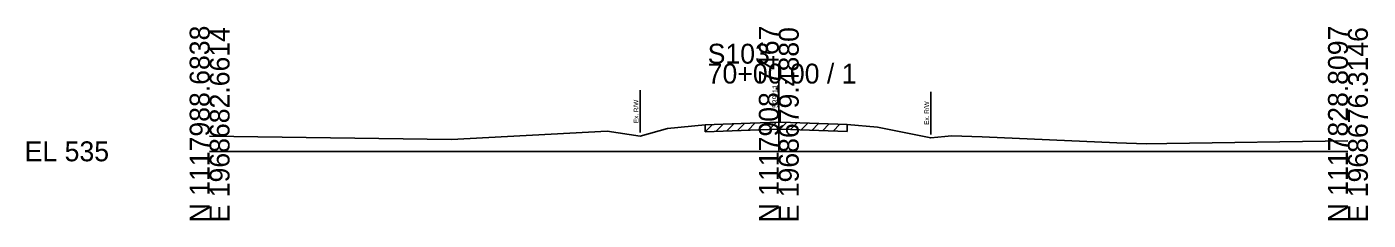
# Model space of a CAD drawing. Extents: x -26 to 163, y -10 to 24018.
# Drawn here: x -25.7 to 162.8, y 17990.3 to 18017.5 of the extents above; entities that cross this region are included whole.
import ezdxf

# ---------------------------------------------------------------- set-up
doc = ezdxf.new("R2010")
doc.units = 0
for name, color, linetype in [('RD_GPK_XS_Cell', 7, 'Continuous'), ('RD_XS_ExGround', 7, 'Continuous'), ('RD_XS_ExPaveRet', 7, 'Continuous'), ('RD_XS_ExRW', 7, 'Continuous'), ('RD_XS_TX_Elev_EX', 7, 'Continuous')]:
    doc.layers.add(name, color=color, linetype=linetype)

msp = doc.modelspace()

# ---------------------------------------------------------------- linework, layer by layer
at = {"layer": 'RD_GPK_XS_Cell'}
for p, q in [((80, 18000), (80, 18012.34)), ((0, 18000), (80, 18000)), ((80, 18000), (160, 18000))]:
    msp.add_line(p, q, dxfattribs=at)
at = {"layer": 'RD_XS_ExGround'}
msp.add_lwpolyline([(0, 18002.15), (33.98, 18001.68), (55.86, 18002.84), (60.51, 18002.13), (64.34, 18003.21), (69.63, 18003.74), (75.97, 18003.96), (80.14, 18004.11), (81.66, 18004.06), (89.61, 18003.77), (93.87, 18003.39), (101.36, 18001.89), (103.33, 18002.1), (104.26, 18002.2), (108.59, 18002.02), (127.49, 18001.22), (131.62, 18001.04), (134.56, 18001.08), (160, 18001.47)], dxfattribs=at)
at = {"layer": 'RD_XS_ExPaveRet'}
for p, q in [((69.63, 18002.74), (70.67, 18003.78)), ((69.63, 18002.74), (69.63, 18003.74)), ((71.13, 18002.79), (72.17, 18003.83)), ((72.63, 18002.85), (73.67, 18003.88)), ((74.13, 18002.9), (75.17, 18003.94)), ((75.63, 18002.95), (76.67, 18003.99)), ((75.97, 18002.96), (80.14, 18003.11)), ((77.13, 18003.01), (78.17, 18004.04)), ((78.63, 18003.06), (79.67, 18004.1)), ((80.13, 18003.11), (81.1, 18004.08)), ((80.14, 18003.11), (81.66, 18003.06)), ((81.63, 18003.06), (82.6, 18004.03)), ((81.66, 18003.06), (89.61, 18002.77)), ((83.13, 18003.01), (84.1, 18003.97)), ((84.63, 18002.95), (85.6, 18003.92)), ((86.13, 18002.9), (87.1, 18003.86)), ((87.63, 18002.84), (88.6, 18003.81)), ((89.61, 18003.77), (89.61, 18002.77)), ((69.63, 18002.74), (75.97, 18002.96))]:
    msp.add_line(p, q, dxfattribs=at)
at = {"layer": 'RD_XS_ExRW'}
for p, q in [((60.51, 18008.63), (60.51, 18002.63)), ((101.36, 18008.39), (101.36, 18002.39))]:
    msp.add_line(p, q, dxfattribs=at)

# ---------------------------------------------------------------- texts
at = {"layer": 'RD_GPK_XS_Cell'}
for s, p in [('N 1117988.6838', (0, 17990)), ('E 1968682.6614', (2.8, 17990)), ('N 1117908.7467', (80, 17990)), ('E 1968679.4880', (82.8, 17990)), ('N 1117828.8097', (160, 17990)), ('E 1968676.3146', (162.8, 17990))]:
    msp.add_text(s, height=2.8, rotation=90, dxfattribs=at).set_placement(p)
for s, p in [('S103', (70, 18012.34)), ('70+00.00 / 1', (70, 18009.54)), ('EL 535', (-26, 17998.6))]:
    msp.add_text(s, height=2.8, dxfattribs=at).set_placement(p)
at = {"layer": 'RD_XS_ExRW'}
for p in [(60.26, 18003.97), (101.11, 18003.74)]:
    msp.add_text('Ex. R/W ', height=0.65, rotation=90, dxfattribs=at).set_placement(p)
at = {"layer": 'RD_XS_TX_Elev_EX'}
msp.add_text('539.11', height=0.8, rotation=90, dxfattribs=at).set_placement((79.9, 18006.11))

doc.saveas('drawing.dxf')
